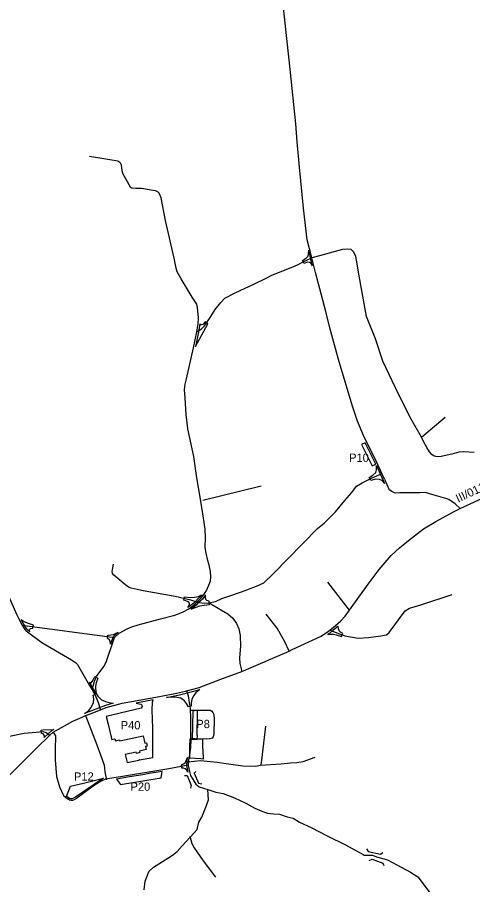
# Model space of a CAD drawing. Extents: x -439169 to -431590, y -1130011 to -1121081.
# Drawn here: x -438294 to -437746, y -1124441 to -1123397 of the extents above; entities that cross this region are included whole.
import ezdxf

# ---------------------------------------------------------------- set-up
doc = ezdxf.new("R2010")
doc.units = 0
for name, color, linetype in [('11811012_místní  komunikace_Stav', 7, 'Continuous'), ('11811022_místní  komunikace_Návrh', 7, 'Continuous'), ('11850012_silnice III třídy_Stav', 7, 'Continuous'), ('11850013_silnice III třídy_Stav', 7, 'Continuous'), ('11900012_účelová komunikace_Stav', 7, 'Continuous'), ('11930011_silniční most _ estakáda_Stav', 7, 'Continuous'), ('12080011_parkoviště mimo prostor komunikace_Stav', 7, 'Continuous'), ('12080013_parkoviště mimo prostor komunikace_Stav', 7, 'Continuous')]:
    doc.layers.add(name, color=color, linetype=linetype)

msp = doc.modelspace()

# ---------------------------------------------------------------- linework, layer by layer
at = {"layer": '11811012_místní  komunikace_Stav'}
for points in [[(-437852, -1123953), (-437861, -1123933.6), (-437877.2, -1123900.5), (-437884.4, -1123883.1), (-437890.4, -1123864.9), (-437895.9, -1123847.7), (-437907.4, -1123808.9), (-437917.7, -1123770.6), (-437922.5, -1123751), (-437935, -1123704.1), (-437939.4, -1123686.2), (-437945, -1123664.7), (-437949.7, -1123626.6), (-437954.5, -1123577.1), (-437957.3, -1123546.5), (-437958.7, -1123524.7), (-437965.7, -1123459.2), (-437971.4, -1123407.3), (-437974.9, -1123373.1)], [(-438204.2, -1124206.8), (-438201.5, -1124196.3), (-438198.8, -1124190.8), (-438195, -1124185.1), (-438189.9, -1124178.1), (-438186.9, -1124172.2), (-438178.8, -1124148.5), (-438177.2, -1124143.9), (-438171.8, -1124138.7), (-438162.2, -1124133.3), (-438156.3, -1124130.7), (-438148.7, -1124128.3), (-438121.7, -1124121.3), (-438104.4, -1124116.9), (-438095.2, -1124113.3), (-438087.7, -1124109.2), (-438080.5, -1124103.7), (-438078.1, -1124101.1), (-438072.8, -1124096.1), (-438070.9, -1124093.5), (-438067, -1124087.8), (-438063.7, -1124080.5), (-438061.7, -1124075.5), (-438061.1, -1124071.1), (-438061.8, -1124064.1), (-438063.4, -1124056.6), (-438064.7, -1124051.1), (-438066.9, -1124042.2), (-438067.9, -1124035.2), (-438067.7, -1124023.1), (-438068.2, -1124013.2), (-438070.3, -1123997.3), (-438073.9, -1123974.6), (-438077.9, -1123951.2), (-438081.7, -1123925.8), (-438089, -1123892.2), (-438090.9, -1123874.9), (-438092.1, -1123855.1), (-438093, -1123844.9), (-438092.3, -1123838.5), (-438090.4, -1123832.1), (-438082.3, -1123794.6), (-438079.9, -1123785.1), (-438077.9, -1123775.4), (-438076.4, -1123765.8), (-438076.2, -1123758.6), (-438077.1, -1123746), (-438078.2, -1123742), (-438083.7, -1123733.6), (-438097.1, -1123711.7), (-438101.9, -1123703.3), (-438102.8, -1123698.6), (-438105.5, -1123686.8), (-438115.8, -1123641.2), (-438121, -1123614), (-438123.5, -1123608.6)], [(-438077.9, -1123775.4), (-438072.9, -1123772.4), (-438068.7, -1123768.1), (-438061.3, -1123757.1), (-438055.8, -1123748.4), (-438049, -1123740), (-438044.4, -1123734.8), (-438032.1, -1123728.4), (-438008.5, -1123717.5), (-437994.5, -1123710.7), (-437987.8, -1123707.2), (-437960.5, -1123696.5), (-437955.9, -1123694.5), (-437949.8, -1123691.2), (-437939.4, -1123686.2)], [(-438329.1, -1124047.2), (-438324.4, -1124051), (-438321.9, -1124055.3), (-438302.4, -1124099.1), (-438295, -1124116.3), (-438292.9, -1124120.6), (-438288.5, -1124128.8), (-438285.2, -1124134), (-438283.6, -1124135.6), (-438265, -1124149.8), (-438229.1, -1124170.6), (-438224.1, -1124173.7), (-438221.7, -1124176.1), (-438218.6, -1124181.9), (-438207.4, -1124201.7), (-438204.2, -1124206.8), (-438201.1, -1124212.4), (-438197.4, -1124221), (-438194, -1124230.7)], [(-438078.1, -1124101.1), (-438085.2, -1124098.7), (-438104.1, -1124094.3), (-438142.8, -1124087.3), (-438157.2, -1124084.4), (-438160.5, -1124082.9), (-438165.5, -1124079), (-438170.7, -1124074.8), (-438178, -1124068.6), (-438179.7, -1124066.6), (-438180.1, -1124064.3), (-438178.4, -1124055.3)], [(-437917.9, -1124134.9), (-437899.9, -1124141.9), (-437883.7, -1124144.5), (-437871.1, -1124143.8), (-437856.3, -1124141.9), (-437849.7, -1124140.5), (-437846.2, -1124137.6), (-437826.9, -1124111.5), (-437821.7, -1124108.3), (-437808.1, -1124104.3), (-437770.5, -1124092.1)], [(-438090.6, -1124208), (-438088.7, -1124214.1), (-438087.4, -1124222.2), (-438086.3, -1124229.3), (-438085.6, -1124241.3), (-438085.6, -1124263.4), (-438085.5, -1124267.4), (-438085.8, -1124276.1), (-438087, -1124285.2), (-438088.3, -1124291.2), (-438088.5, -1124297.8), (-438087, -1124305.3), (-438085.6, -1124309.8), (-438082.6, -1124315.3), (-438079.2, -1124320.6), (-438075.2, -1124323.7), (-438064.7, -1124327), (-438055.2, -1124330.1), (-438046.4, -1124331.8), (-438032.7, -1124336.9), (-438019.2, -1124343.2), (-438008.1, -1124349.3), (-437999.7, -1124353.1), (-437995.5, -1124354.7), (-437993.1, -1124355.4), (-437985.6, -1124356.2), (-437978.5, -1124356.4), (-437969.2, -1124359.6), (-437962, -1124361.2), (-437954.3, -1124366), (-437940.5, -1124372.8), (-437921.1, -1124382.7), (-437899.1, -1124393.4), (-437877.8, -1124405.2), (-437876.4, -1124405.9), (-437872, -1124405.9), (-437866.5, -1124406.1), (-437861.7, -1124407.8), (-437848.2, -1124411.6), (-437820.8, -1124426.5), (-437812, -1124432.2), (-437782.7, -1124471)], [(-438400.7, -1124243.9), (-438386.1, -1124240.1), (-438376, -1124238), (-438368.6, -1124235.9), (-438365.4, -1124235.7), (-438362, -1124235.5), (-438357.5, -1124239.2), (-438349.4, -1124250.1), (-438341.1, -1124259.3), (-438337.2, -1124264.6), (-438332, -1124266.7), (-438327.8, -1124266.7), (-438316.4, -1124265), (-438303.7, -1124262.4), (-438286, -1124259.1), (-438271.8, -1124257.6), (-438263.7, -1124257.1), (-438259.8, -1124258.2), (-438255.1, -1124261.2)], [(-438088.9, -1124293.7), (-438073.5, -1124291.8), (-438053.6, -1124294.1), (-438042.9, -1124295.4)], [(-438141.5, -1124447.9), (-438140.2, -1124437.3), (-438138, -1124431.2), (-438135.9, -1124425.5), (-438130.4, -1124420.6), (-438124, -1124416.5), (-438107.6, -1124405.9), (-438101.9, -1124401.4), (-438095.9, -1124394.6), (-438081.2, -1124379), (-438077.7, -1124374.9), (-438075.6, -1124366.3), (-438072.2, -1124360), (-438067.1, -1124348.2), (-438064.2, -1124339.4), (-438064.7, -1124327)]]:
    msp.add_lwpolyline(points, dxfattribs=at)
for points in [[(-437948.9, -1123693), (-437950.7, -1123689.4), (-437946.4, -1123686.7), (-437944.5, -1123684.7), (-437943.4, -1123682.2), (-437943, -1123677.1), (-437941.4, -1123686.6), (-437939.1, -1123696), (-437940.5, -1123693.2), (-437942.4, -1123692), (-437945.2, -1123691.7)], [(-438079.8, -1123793), (-438064.7, -1123765.7), (-438068, -1123763.5), (-438070.8, -1123766.7), (-438072.5, -1123767.2), (-438073.7, -1123766.9), (-438074.4, -1123766), (-438075.9, -1123775.7)], [(-437879.7, -1123911.1), (-437866.9, -1123936.8), (-437862.6, -1123934.8), (-437875.1, -1123909.2)], [(-438093.9, -1124098.7), (-438093, -1124094.8), (-438085.3, -1124095.6), (-438080.9, -1124095.3), (-438076.2, -1124094.4), (-438072.6, -1124092.4), (-438074.3, -1124094.8), (-438081.9, -1124102.2), (-438088.8, -1124107.6), (-438087.1, -1124104.4), (-438087.1, -1124102.5), (-438088.3, -1124100.8)], [(-437920.7, -1124140.3), (-437917.2, -1124139.7), (-437913.5, -1124139.9), (-437910.4, -1124140.5), (-437903.7, -1124142.6), (-437902.2, -1124138.9), (-437905.1, -1124137.2), (-437906.5, -1124135.6), (-437907.6, -1124133.2), (-437907.9, -1124130.1), (-437914.1, -1124135.4), (-437917.8, -1124138.4)], [(-438207.4, -1124197.5), (-438206.1, -1124198.1), (-438204.9, -1124197.8), (-438204, -1124196.8), (-438203.4, -1124195.6), (-438201, -1124190.8), (-438197.5, -1124192.6), (-438199.3, -1124198.2), (-438200.1, -1124202.5), (-438200.3, -1124205.1), (-438199.4, -1124211.3)], [(-438088.3, -1124227.3), (-438090.7, -1124223.1), (-438092.8, -1124220.1), (-438097.2, -1124216.7), (-438104.5, -1124215.6), (-438114.8, -1124216), (-438099, -1124212.8), (-438083.4, -1124208.9), (-438074.3, -1124206.5), (-438079.3, -1124210.5), (-438082.2, -1124213.9), (-438084, -1124218.5), (-438084.9, -1124222.8), (-438084.9, -1124226.5)], [(-438213.3, -1124235.3), (-438208.6, -1124231.9), (-438205.2, -1124228), (-438202.6, -1124222), (-438202.1, -1124217.5), (-438202.9, -1124213.3), (-438199.4, -1124211.3), (-438197.2, -1124214.4), (-438192.8, -1124219), (-438188.2, -1124220.8), (-438182.7, -1124222.3), (-438178.8, -1124223), (-438188.3, -1124225.5)], [(-438265.3, -1124259.2), (-438265.6, -1124255.2), (-438263.5, -1124255), (-438250.5, -1124254.4), (-438252.6, -1124255.6), (-438257, -1124259.2), (-438262.1, -1124264.2), (-438261.7, -1124262.4), (-438262.1, -1124261.2), (-438263.3, -1124259.7)], [(-438096, -1124301), (-438096.7, -1124297), (-438094.1, -1124296.1), (-438092.3, -1124294.6), (-438091.5, -1124293), (-438089.5, -1124288.4), (-438090.3, -1124291.2), (-438090.5, -1124298), (-438089, -1124305.8), (-438090.6, -1124303.1), (-438092.3, -1124301.9), (-438094.1, -1124301.3)]]:
    msp.add_lwpolyline(points, close=True, dxfattribs=at)
at = {"layer": '11811022_místní  komunikace_Návrh'}
for p, q in [((-437852, -1123953), (-437846.2, -1123966)), ((-438288.5, -1124128.8), (-438177.2, -1124143.9))]:
    msp.add_line(p, q, dxfattribs=at)
for points in [[(-437851.8, -1123958.3), (-437855.3, -1123954.4), (-437858, -1123953.2), (-437862.8, -1123952.9), (-437868.4, -1123954.5), (-437870.3, -1123950.9), (-437866, -1123948.3), (-437862.5, -1123944.9), (-437861.5, -1123941.7), (-437861.7, -1123936.6)], [(-438062.9, -1124104.1), (-438063.4, -1124100.1), (-438066.2, -1124099.1), (-438067.4, -1124097.9), (-438067.7, -1124095.3), (-438067.7, -1124092.4), (-438071.3, -1124097.4), (-438076.7, -1124102.5), (-438078.5, -1124104.5), (-438085, -1124109.7), (-438079, -1124107), (-438074.3, -1124105.7), (-438069.1, -1124104.8)], [(-438279.4, -1124136.3), (-438279.6, -1124134.8), (-438279.3, -1124133.6), (-438278.5, -1124132.9), (-438275.6, -1124132.6), (-438274.8, -1124128.7), (-438280.9, -1124127), (-438286.2, -1124124.8), (-438289.6, -1124122.5), (-438286.8, -1124127.8), (-438283.7, -1124132.7), (-438282.3, -1124134.1)], [(-438185.8, -1124144.8), (-438185.2, -1124140.8), (-438181.9, -1124140.7), (-438178.6, -1124140.3), (-438173, -1124137.1), (-438178.9, -1124142.8), (-438180.8, -1124148), (-438182, -1124151.6), (-438182.5, -1124148.5), (-438183.4, -1124146.6)]]:
    msp.add_lwpolyline(points, close=True, dxfattribs=at)
for points in [[(-438078.1, -1124101.1), (-438068.7, -1124102.3), (-438063.2, -1124102.1), (-438055.5, -1124100.3), (-438047.8, -1124096.6), (-438039.5, -1124094.1), (-438024.1, -1124088.6), (-438006.1, -1124082), (-437997.3, -1124077.7), (-437986.1, -1124067.2), (-437932.7, -1124012.6), (-437924.8, -1124006.1), (-437911.2, -1123992.3), (-437899.6, -1123978.8), (-437891.5, -1123968.9), (-437885.6, -1123961.5), (-437879, -1123957.2), (-437866.7, -1123951.3), (-437854.6, -1123946.1)], [(-438088.5, -1124297.6), (-438111.8, -1124301.8), (-438169.9, -1124311.4), (-438178.2, -1124312.9), (-438188, -1124314.2), (-438194, -1124317.1), (-438203, -1124322.9), (-438223.1, -1124337.8), (-438225.8, -1124339.2), (-438227.8, -1124339.9), (-438229.3, -1124340), (-438231.6, -1124339.8), (-438233.8, -1124338.1)]]:
    msp.add_lwpolyline(points, dxfattribs=at)
at = {"layer": '11850012_silnice III třídy_Stav'}
msp.add_lwpolyline([(-438345.4, -1124350.8), (-438271.3, -1124277.1), (-438255.1, -1124261.2), (-438251.1, -1124257.9), (-438244.8, -1124254.2), (-438234.1, -1124248), (-438227.5, -1124244.6), (-438216.1, -1124239.6), (-438212.2, -1124237.8), (-438207.3, -1124235.9), (-438194, -1124230.7), (-438187.4, -1124228.1), (-438168.2, -1124223), (-438122.9, -1124214.9), (-438102.6, -1124210.8), (-438091.8, -1124208.4), (-438075.1, -1124203.9), (-438049.3, -1124193.9), (-438023.9, -1124184.8), (-437966.8, -1124160), (-437963.4, -1124158.2), (-437928.3, -1124142.1), (-437919.4, -1124136.2), (-437913.9, -1124131.7), (-437904.7, -1124123.6), (-437899.5, -1124118.2), (-437894, -1124110.9), (-437871.5, -1124079.4), (-437858.6, -1124061.7), (-437851.2, -1124053.2), (-437843.9, -1124045.1), (-437833.9, -1124035.5), (-437822.9, -1124026.7), (-437804.9, -1124012.8), (-437790.1, -1124003.9), (-437768.7, -1123992.5), (-437761, -1123988.4), (-437720.1, -1123969.3)], dxfattribs=at)
at = {"layer": '11900012_účelová komunikace_Stav'}
for p, q in [((-437807.4, -1123902.5), (-437778.7, -1123878.2)), ((-438070.7, -1123978.1), (-438000.5, -1123961.1)), ((-437894, -1124110.9), (-437920.3, -1124077.1))]:
    msp.add_line(p, q, dxfattribs=at)
for points in [[(-438207.6, -1123563.9), (-438185.3, -1123567.3), (-438173.4, -1123569.6), (-438170.8, -1123571.2), (-438169.1, -1123574.3), (-438168.3, -1123581.3), (-438167.1, -1123585.2), (-438158.4, -1123600.8), (-438156.5, -1123601.9), (-438151.7, -1123602.3), (-438144.9, -1123602.5), (-438128.3, -1123605.1), (-438125.2, -1123606.7), (-438123.5, -1123608.6)], [(-437743.9, -1123920.8), (-437756.4, -1123920), (-437762.5, -1123920.6), (-437770.7, -1123922.7), (-437783.7, -1123925.7), (-437788.1, -1123925.9), (-437792, -1123925.1), (-437795.1, -1123923.4), (-437797.9, -1123920), (-437800.8, -1123914.7), (-437804.5, -1123908.4), (-437807.4, -1123902.5), (-437820, -1123880.6), (-437835.3, -1123850.7), (-437853.9, -1123811), (-437863, -1123783.8), (-437873.6, -1123757.2), (-437883.2, -1123703.5), (-437884.8, -1123693.7), (-437886.5, -1123684.6), (-437889, -1123679.3), (-437892.3, -1123676.1), (-437896.6, -1123675.9), (-437902.5, -1123676.3), (-437911.3, -1123678.7), (-437930.3, -1123683.9), (-437939.4, -1123686.2)], [(-437761, -1123988.4), (-437766.8, -1123982.5), (-437774.3, -1123977.3), (-437778.2, -1123976.2), (-437797.9, -1123970.5), (-437802.5, -1123969.2), (-437809.5, -1123969.4), (-437822.6, -1123969.4), (-437833.4, -1123969.6), (-437839.3, -1123969.8), (-437843.3, -1123968), (-437846.2, -1123966)], [(-438063.2, -1124102.1), (-438048.4, -1124110.6), (-438040.8, -1124115.3), (-438034.9, -1124120.5), (-438030.4, -1124126.8), (-438027.4, -1124133.4), (-438025.9, -1124141.3), (-438025.6, -1124154.3), (-438026.6, -1124168.2), (-438026.2, -1124175.1), (-438023.9, -1124184.8)], [(-437966.8, -1124160), (-437971.9, -1124148.9), (-437981.3, -1124132.3), (-437994.4, -1124115.6)], [(-438212.2, -1124237.8), (-438198.6, -1124273), (-438194, -1124285), (-438189.9, -1124297.7), (-438189, -1124305.7), (-438186.8, -1124315.2)], [(-438085.7, -1124231.2), (-438071.8, -1124231.1), (-438064.1, -1124231.1), (-438061.9, -1124231.4), (-438060.1, -1124232.3), (-438058.7, -1124234.1), (-438057.6, -1124236.5), (-438057.1, -1124241.7), (-438057.8, -1124259.7), (-438058.3, -1124263.3), (-438059.8, -1124265.1), (-438062.5, -1124265.9), (-438066.3, -1124266.1), (-438080, -1124266), (-438085.7, -1124265.6)], [(-438000.6, -1124297.3), (-437999.6, -1124291.6), (-437995, -1124250.7)], [(-438251.1, -1124257.9), (-438248.5, -1124262.1), (-438248.5, -1124265.8), (-438248.9, -1124275.4), (-438248.9, -1124290.9), (-438247, -1124311.2), (-438243.7, -1124323.7), (-438238.9, -1124334), (-438233.8, -1124338.1)], [(-438042.9, -1124295.4), (-438022.5, -1124298.2), (-438007.2, -1124298.9), (-438001.8, -1124297.6), (-437976.3, -1124296.1), (-437965.4, -1124294.8), (-437957.6, -1124294.2), (-437949.9, -1124293), (-437935.6, -1124287.7)], [(-438086.5, -1124383.1), (-438084.3, -1124392), (-438081.5, -1124397.1), (-438070.5, -1124412.6), (-438055.5, -1124432.5)]]:
    msp.add_lwpolyline(points, dxfattribs=at)
at = {"layer": '11930011_silniční most _ estakáda_Stav'}
for points in [[(-438093.1, -1124309.8), (-438089.8, -1124309.8), (-438085, -1124321.9), (-438085.6, -1124325.1)], [(-438079.3, -1124305), (-438081.5, -1124307), (-438076.2, -1124319.3), (-438072.1, -1124319.9)], [(-437873.5, -1124398.4), (-437871.5, -1124401.6), (-437856.9, -1124404.7), (-437854, -1124402.9)], [(-437870.4, -1124412.3), (-437866.7, -1124410.6), (-437854, -1124415.7), (-437852.7, -1124418.5)]]:
    msp.add_lwpolyline(points, dxfattribs=at)
at = {"layer": '12080011_parkoviště mimo prostor komunikace_Stav'}
for p, q in [((-438081.9, -1124231.7), (-438082, -1124232.8)), ((-438077.3, -1124231.6), (-438081.9, -1124231.7)), ((-438077.4, -1124235.4), (-438077.3, -1124231.6)), ((-438083.9, -1124266.3), (-438077.6, -1124266.5)), ((-438077.6, -1124266.5), (-438077.4, -1124261.6)), ((-438162.2, -1124294.3), (-438147.9, -1124291.4)), ((-438147.2, -1124291.3), (-438131.3, -1124288.1)), ((-438159.1, -1124311.6), (-438174.9, -1124314.2)), ((-438230.8, -1124337.9), (-438235.2, -1124335.2))]:
    msp.add_line(p, q, dxfattribs=at)
for points in [[(-438131, -1124253.4), (-438132.1, -1124230.7), (-438131.6, -1124221.8), (-438130.6, -1124219), (-438151.3, -1124222.7), (-438145.7, -1124223.9), (-438144.3, -1124225.2), (-438143.8, -1124226.9), (-438145.2, -1124228.9)], [(-438145.2, -1124228.9), (-438187.4, -1124238.8), (-438185.1, -1124248.2), (-438181.3, -1124263.6), (-438180.6, -1124266.5), (-438176.7, -1124265.6), (-438176.2, -1124268.1), (-438171.2, -1124267), (-438170.9, -1124268.4), (-438142.9, -1124262)], [(-438082, -1124232.8), (-438083.1, -1124232.8), (-438083.9, -1124266.3)], [(-438077.4, -1124261.6), (-438077.5, -1124261.6), (-438077.4, -1124235.4), (-438077.4, -1124235.4)], [(-438131.3, -1124288.1), (-438131.3, -1124272.5), (-438131, -1124253.4)], [(-438142.9, -1124262), (-438140.8, -1124271.2), (-438138.8, -1124270.7), (-438137.9, -1124274.7), (-438139.9, -1124275.2), (-438139.1, -1124278.7), (-438147.1, -1124280.5), (-438146.6, -1124282.4), (-438150.9, -1124283.3), (-438151.2, -1124281.7), (-438164.4, -1124284.7), (-438162.2, -1124294.3)], [(-438235.2, -1124335.2), (-438230.3, -1124323), (-438214.5, -1124319.1), (-438190.7, -1124313), (-438215.4, -1124330.2), (-438224.1, -1124336.1), (-438226.5, -1124337.4), (-438228.2, -1124337.9), (-438229.3, -1124338), (-438230.8, -1124337.9)], [(-438174.9, -1124314.2), (-438170.1, -1124321), (-438121.2, -1124312.7), (-438120.1, -1124307.5), (-438119.7, -1124305.1), (-438135.5, -1124307.7), (-438143.3, -1124309), (-438159.1, -1124311.6)]]:
    msp.add_lwpolyline(points, dxfattribs=at)
msp.add_lwpolyline([(-438086.3, -1124265.8), (-438080, -1124266), (-438071.3, -1124266.1), (-438071.3, -1124274), (-438070.4, -1124288.6), (-438070.2, -1124290.2), (-438073.4, -1124289.9), (-438086.4, -1124289.2), (-438086.6, -1124283.3), (-438086.7, -1124274.5)], close=True, dxfattribs=at)
msp.add_arc((-438147.5, -1124291.7), 0.5, 58.4212, 144.3772, dxfattribs=at)

# ---------------------------------------------------------------- texts
at = {"layer": '11850013_silnice III třídy_Stav'}
msp.add_text('III/011446', height=10, rotation=25.1695, dxfattribs=at).set_placement((-437763.2, -1123981.4))
at = {"layer": '12080013_parkoviště mimo prostor komunikace_Stav'}
for s, p in [('P10', (-437894.6, -1123932.1)), ('P40', (-438169.8, -1124254.4)), ('P8', (-438078.7, -1124252.9)), ('P12', (-438226.1, -1124316.2)), ('P20', (-438158, -1124328.4))]:
    msp.add_text(s, height=10, dxfattribs=at).set_placement(p)

doc.saveas('drawing.dxf')
